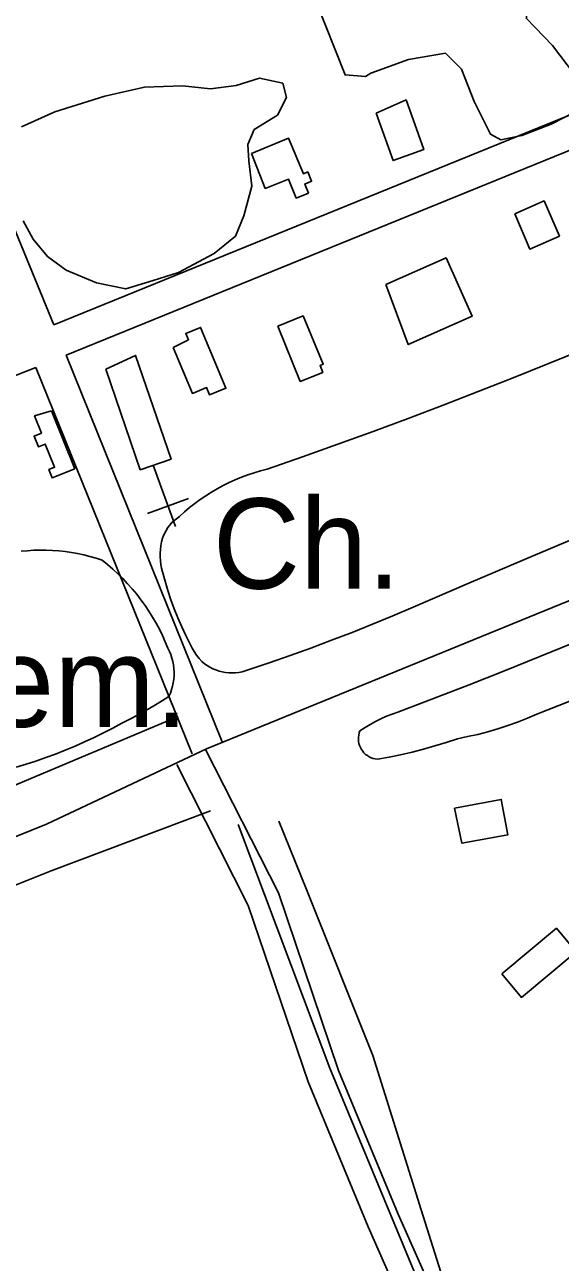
# Model space of a CAD drawing. Extents: x 3568792 to 3606828, y 529143 to 554785.
# Drawn here: x 3573187 to 3573679, y 535909 to 537047 of the extents above; entities that cross this region are included whole.
import ezdxf

# ---------------------------------------------------------------- set-up
doc = ezdxf.new("R2010")
doc.units = 0
for name, color, linetype in [('V-BLDG-OTLN', 7, 'Continuous'), ('V-DTCH-CNTR', 7, 'Continuous'), ('V-ROAD-CNTR', 7, 'Continuous'), ('V-SITE-OTLN', 7, 'Continuous'), ('V-SITE-OTLN-IDEN', 7, 'Continuous'), ('V-SITE-VEGE', 7, 'Continuous'), ('V-TOPO-SHOR', 7, 'Continuous')]:
    doc.layers.add(name, color=color, linetype=linetype)

msp = doc.modelspace()

# ---------------------------------------------------------------- linework, layer by layer
at = {"layer": 'V-BLDG-OTLN'}
for points in [[(3573509.4, 536966.2), (3573536.9, 536978.3), (3573553.2, 536932.6), (3573525, 536922.5)], [(3573395, 536929.2), (3573428.9, 536943.3), (3573442.6, 536910.4), (3573446.6, 536912.1), (3573450.2, 536903.6), (3573443.9, 536901), (3573447.3, 536892.7), (3573436, 536888), (3573428.8, 536905.6), (3573407.5, 536896.9)], [(3573636.9, 536873.6), (3573663.7, 536885.4), (3573677.9, 536853.1), (3573650.6, 536841.1)], [(3573518.4, 536808.5), (3573573.7, 536833.1), (3573597.6, 536779.4), (3573539, 536753.3)], [(3573419.2, 536770.2), (3573442.3, 536779.7), (3573460.9, 536735.4), (3573457.9, 536734.1), (3573460.4, 536727.8), (3573439.8, 536719.5)], [(3573323.1, 536750.7), (3573337, 536757.8), (3573334.6, 536763.5), (3573348.1, 536769.1), (3573371.5, 536713.2), (3573356.4, 536707), (3573353.6, 536713.8), (3573340.7, 536708.5)], [(3573261.1, 536730.6), (3573288.5, 536743.4), (3573321, 536648), (3573292.7, 536638.3)], [(3573211.1, 536692.3), (3573232.5, 536639.2), (3573211.8, 536630.8), (3573208.8, 536638.4), (3573214.1, 536640.6), (3573205.5, 536661.9), (3573199.1, 536659.3), (3573195.2, 536669.1), (3573202, 536671.9), (3573195.6, 536687.8)], [(3573581.6, 536327.1), (3573624.4, 536335), (3573630.5, 536302.5), (3573588.3, 536294.7)], [(3573624.8, 536174.7), (3573675.1, 536216.6), (3573693.2, 536195), (3573642.9, 536153)]]:
    msp.add_lwpolyline(points, close=True, dxfattribs=at)
at = {"layer": 'V-DTCH-CNTR'}
msp.add_lwpolyline([(3573382.6, 536312), (3573467, 536088), (3573556.3, 535872.2)], dxfattribs=at)
at = {"layer": 'V-ROAD-CNTR'}
for p, q in [((3572993.9, 537306.3), (3573213.3, 536771.4)), ((3573224.7, 536743.6), (3573368.1, 536388.1)), ((3573196.8, 536732.4), (3572510.1, 536458.8)), ((3573196.8, 536732.4), (3573340.3, 536376.9))]:
    msp.add_line(p, q, dxfattribs=at)
for points in [[(3574339.3, 537227.7), (3574291.9, 537210.9), (3573213.3, 536771.4)], [(3574349.4, 537199.4), (3574302.6, 537182.8), (3573224.7, 536743.6)], [(3574422.7, 536818.6), (3573353.7, 536381.5)], [(3573353.7, 536381.5), (3573206.6, 536312.3), (3572921.5, 536197.1), (3572503.3, 536024.2), (3572162.1, 535884.9), (3571862.4, 535763.3), (3571522.7, 535625.9), (3571137.7, 535472.3), (3571071.3, 535445.2)], [(3574583.8, 536038.1), (3574444.3, 536015.3), (3574188.8, 535966.9), (3573911.7, 535913.3), (3573704.3, 535870.1), (3573650.4, 535865.4), (3573596.8, 535854.9), (3573581.3, 535855.2), (3573570.6, 535861.2), (3573529.7, 535953.7), (3573475, 536085.7), (3573419.6, 536249.1), (3573352.8, 536381)], [(3574588.6, 536008.4), (3574449.5, 535985.7), (3574194.4, 535937.4), (3573917.6, 535883.9), (3573708.7, 535840.3), (3573654.6, 535835.6), (3573599.4, 535824.9), (3573573.2, 535825.3), (3573547.2, 535840), (3573502.1, 535941.9), (3573446.9, 536075.2), (3573391.9, 536237.4), (3573326.2, 536367.1)]]:
    msp.add_lwpolyline(points, dxfattribs=at)
at = {"layer": 'V-SITE-OTLN'}
for p, q in [((3573304.7, 536642.5), (3573325.2, 536586.1)), ((3573299.5, 536598), (3573337.1, 536611.7))]:
    msp.add_line(p, q, dxfattribs=at)
at = {"layer": 'V-SITE-VEGE'}
for p, q in [((3573183.2, 536563.3), (3573189, 536563.8)), ((3573189, 536563.8), (3573194.8, 536564.2)), ((3573194.8, 536564.2), (3573200.6, 536564.4)), ((3573200.6, 536564.4), (3573206.4, 536564.3)), ((3573206.4, 536564.3), (3573212.2, 536564.1)), ((3573212.2, 536564.1), (3573218, 536563.6)), ((3573218, 536563.6), (3573223.8, 536563)), ((3573223.8, 536563), (3573229.5, 536562.1)), ((3573229.5, 536562.1), (3573235.2, 536561.1)), ((3573235.2, 536561.1), (3573240.9, 536559.9)), ((3573240.9, 536559.9), (3573246.5, 536558.4)), ((3573246.5, 536558.4), (3573252.1, 536556.8)), ((3573252.1, 536556.8), (3573257.6, 536555)), ((3573257.6, 536555), (3573262.6, 536551)), ((3573262.6, 536551), (3573267.5, 536546.9)), ((3573267.5, 536546.9), (3573272.2, 536542.5)), ((3573272.2, 536542.5), (3573276.7, 536538.1)), ((3573276.7, 536538.1), (3573281.1, 536533.4)), ((3573281.1, 536533.4), (3573285.4, 536528.7)), ((3573285.4, 536528.7), (3573289.5, 536523.8)), ((3573289.5, 536523.8), (3573293.4, 536518.7)), ((3573293.4, 536518.7), (3573297.1, 536513.5)), ((3573297.1, 536513.5), (3573300.7, 536508.2)), ((3573300.7, 536508.2), (3573304.1, 536502.8)), ((3573304.1, 536502.8), (3573307.3, 536497.3)), ((3573307.3, 536497.3), (3573310.3, 536491.7)), ((3573310.3, 536491.7), (3573313.1, 536485.9)), ((3573313.1, 536485.9), (3573315.7, 536480.1)), ((3573315.7, 536480.1), (3573318.1, 536474.2)), ((3573318.1, 536474.2), (3573319.6, 536471.2)), ((3573319.6, 536471.2), (3573320.8, 536468.2)), ((3573320.8, 536468.2), (3573321.8, 536465.1)), ((3573321.8, 536465.1), (3573322.7, 536461.9)), ((3573322.7, 536461.9), (3573323.3, 536458.7)), ((3573323.3, 536458.7), (3573323.7, 536455.4)), ((3573323.7, 536455.4), (3573323.8, 536452.1)), ((3573323.1, 536442.3), (3573322.4, 536439.1)), ((3573323.6, 536445.6), (3573323.1, 536442.3)), ((3573323.8, 536448.8), (3573323.6, 536445.6)), ((3573323.8, 536452.1), (3573323.8, 536448.8)), ((3573320.4, 536432.9), (3573319.1, 536429.8)), ((3573321.5, 536436), (3573320.4, 536432.9)), ((3573322.4, 536439.1), (3573321.5, 536436)), ((3573305.1, 536421), (3573297.9, 536416.8)), ((3573312.2, 536425.3), (3573305.1, 536421)), ((3573319.1, 536429.8), (3573312.2, 536425.3)), ((3573283.3, 536409), (3573275.8, 536405.3)), ((3573290.7, 536412.8), (3573283.3, 536409)), ((3573297.9, 536416.8), (3573290.7, 536412.8)), ((3573258.9, 536396.3), (3573250.3, 536392)), ((3573267.4, 536400.7), (3573258.9, 536396.3)), ((3573275.8, 536405.3), (3573267.4, 536400.7)), ((3573241.6, 536387.9), (3573232.8, 536384)), ((3573250.3, 536392), (3573241.6, 536387.9)), ((3573206, 536373.5), (3573196.9, 536370.3)), ((3573215, 536376.8), (3573206, 536373.5)), ((3573223.9, 536380.3), (3573215, 536376.8)), ((3573232.8, 536384), (3573223.9, 536380.3)), ((3573187.8, 536367.4), (3573178.6, 536364.6)), ((3573196.9, 536370.3), (3573187.8, 536367.4))]:
    msp.add_line(p, q, dxfattribs=at)
for points in [[(3573681.7, 537127.1), (3573660.1, 537105.5), (3573648.6, 537086.9), (3573647.5, 537053.2), (3573671.5, 537028.4), (3573691.7, 537001.8)], [(3573692.4, 536967.4), (3573670.4, 536955.9), (3573643.3, 536945.7), (3573623.9, 536941.6), (3573614.6, 536946.7), (3573599.4, 536977), (3573588, 537006.6), (3573573.2, 537021.2), (3573539.3, 537015.4), (3573504.7, 537002.8), (3573499.7, 536999.8), (3573481, 537001.3), (3573434, 537119.6)], [(3573183.5, 536953.6), (3573214.4, 536967.5), (3573260.2, 536981.8), (3573296.6, 536990), (3573331.7, 536991.4), (3573357.3, 536988.5), (3573380.8, 536991.7), (3573402.4, 536998.4), (3573423.6, 536993.7), (3573427.2, 536980.5), (3573418.8, 536964.4), (3573397.3, 536951), (3573391.5, 536937.3), (3573392.5, 536922.3), (3573395.3, 536899.1), (3573388, 536871.7), (3573380.2, 536853.1), (3573360.6, 536837.1), (3573327.8, 536819.5), (3573304.6, 536812.3), (3573279.4, 536804.6), (3573252.6, 536810), (3573224.7, 536821.7), (3573207.4, 536834.4), (3573194.5, 536850.3), (3573185.3, 536867.3)], [(3573313.1, 536544.4), (3573312.3, 536547.8), (3573311.6, 536551.2), (3573311.2, 536554.6), (3573311, 536558.1), (3573311, 536561.5), (3573311.3, 536565), (3573311.7, 536568.4), (3573312.4, 536571.8), (3573313.3, 536575.2), (3573314.2, 536577.8), (3573318.2, 536585.1), (3573322.2, 536589.9), (3573328.7, 536595.2), (3573333.3, 536599.4), (3573338, 536603.4), (3573342.8, 536607.2), (3573347.8, 536610.9), (3573352.9, 536614.4), (3573358.1, 536617.7), (3573363.4, 536620.8), (3573368.8, 536623.7), (3573374.4, 536626.5), (3573380, 536629), (3573385.7, 536631.4), (3573391.5, 536633.5), (3573397.3, 536635.5), (3573403.3, 536637.2), (3573409.2, 536638.8), (3573441.7, 536650.1), (3573474.2, 536661.7), (3573506.6, 536673.5), (3573538.8, 536685.5), (3573571.1, 536697.7), (3573603.2, 536710.1), (3573635.3, 536722.8), (3573667.2, 536735.6), (3573699.1, 536748.6)], [(3573697.1, 536577.6), (3573645.9, 536555.8), (3573594.7, 536533.9), (3573543.6, 536511.9), (3573524.9, 536503.9), (3573506.2, 536496.2), (3573487.4, 536488.7), (3573468.5, 536481.4), (3573449.5, 536474.3), (3573430.5, 536467.4), (3573411.3, 536460.8), (3573389.2, 536453.3), (3573386.3, 536452.5), (3573383.3, 536451.9), (3573380.3, 536451.6), (3573377.2, 536451.4), (3573374.2, 536451.5), (3573371.1, 536451.8), (3573368.1, 536452.4), (3573365.2, 536453.1), (3573362.3, 536454.1), (3573359.5, 536455.2), (3573356.8, 536456.6), (3573354.1, 536458.2), (3573351.7, 536459.9), (3573349.3, 536461.9), (3573346.8, 536464.8), (3573344.5, 536467.8), (3573342.4, 536471), (3573340.4, 536474.3), (3573338.6, 536477.7), (3573334.6, 536485.7), (3573330.8, 536493.8), (3573327.3, 536502), (3573324, 536510.3), (3573320.9, 536518.7), (3573318.1, 536527.2), (3573315.5, 536535.8), (3573313.1, 536544.4)], [(3573493.2, 536390.4), (3573493.2, 536392.3), (3573493.5, 536394.3), (3573494, 536396.2), (3573494.6, 536398.1), (3573499.3, 536401.2), (3573504, 536404.1), (3573508.9, 536406.8), (3573513.9, 536409.2), (3573519, 536411.5), (3573524.2, 536413.5), (3573529.5, 536415.4), (3573562.2, 536427.8), (3573594.8, 536440.5), (3573627.4, 536453.4), (3573659.9, 536466.4), (3573692.3, 536479.7)], [(3573707.6, 536433.4), (3573657.2, 536413.4), (3573648.4, 536409.7), (3573639.4, 536406.2), (3573630.3, 536403), (3573621.2, 536399.9), (3573612, 536397.3), (3573602.8, 536394.9), (3573593.5, 536392.8), (3573584.1, 536390.8), (3573573.8, 536387.4), (3573563.5, 536384.2), (3573553, 536381.3), (3573542.5, 536378.6), (3573531.9, 536376.2), (3573521.3, 536374), (3573510.6, 536372.1), (3573508.6, 536372.3), (3573506.7, 536372.8), (3573504.8, 536373.4), (3573503.1, 536374.2), (3573501.4, 536375.3), (3573499.8, 536376.5), (3573498.3, 536377.8), (3573497.1, 536379.3), (3573495.9, 536381), (3573495, 536382.7), (3573494.2, 536384.5), (3573493.7, 536386.4), (3573493.3, 536388.4), (3573493.2, 536390.4)]]:
    msp.add_lwpolyline(points, dxfattribs=at)
at = {"layer": 'V-TOPO-SHOR'}
for points in [[(3573327.5, 536411.2), (3573015.9, 536280), (3572780.9, 536192.9), (3572527.3, 536090.5)], [(3572049.2, 535793.2), (3572332.1, 535910.9), (3572561.1, 536002.5), (3572798, 536099.3), (3573006.8, 536187.9), (3573211, 536269.4), (3573357.2, 536324.6)], [(3574557.4, 536040.1), (3574387, 536006.7), (3574193.8, 535970.5), (3573958.5, 535925.7), (3573744.6, 535884.2), (3573647.2, 535865.8), (3573608.9, 535859), (3573592.1, 535858.4), (3573585.2, 535860.3), (3573580, 535865.3), (3573577.8, 535872.1), (3573550.7, 535957.6), (3573506.4, 536099.7), (3573445.5, 536252.3), (3573420, 536315.2)]]:
    msp.add_lwpolyline(points, dxfattribs=at)

# ---------------------------------------------------------------- texts
at = {"layer": 'V-SITE-OTLN-IDEN'}
for s, p in [('Ch.', (3573359.4, 536528.9)), ('Cem.', (3573071.8, 536401.8))]:
    msp.add_text(s, height=83, dxfattribs=at).set_placement(p)

doc.saveas('drawing.dxf')
